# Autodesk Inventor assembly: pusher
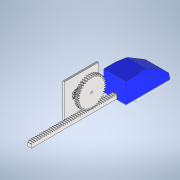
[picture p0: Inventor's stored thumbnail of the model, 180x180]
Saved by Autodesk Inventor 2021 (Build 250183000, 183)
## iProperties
Created: 2026-10
Part Number: pusher
Document SubType Name: Assembly
Designer: alolo
Author: alolo
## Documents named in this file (7)
- C:\Users\hp\Documents\Inventor\DOM1_CartesianRobot\pusher.iam
- C:\Users\hp\Documents\Inventor\DOM1_CartesianRobot\pusher_pinion.ipt
- C:\Users\hp\Documents\Inventor\DOM1_CartesianRobot\Servo MG996R.ipt
- C:\Users\hp\Documents\Inventor\DOM1_CartesianRobot\pusher_rack.ipt
- C:\Users\hp\Documents\Inventor\DOM1_CartesianRobot\pusher_base.ipt
- C:\Users\hp\Documents\Inventor\DOM1_CartesianRobot\pusher_support.ipt
- C:\Users\hp\Documents\Inventor\DOM1_CartesianRobot\pusher_punch.ipt
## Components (6 placed, 6 different names)
1. Servo MG996R:1 — Angle:1, Mate:8, Mate:9, Mate:10, Rotational:1
2. pusher_base:1 — Mate:1, Mate:2, Mate:11, Slider:2, Flush:2, Mate:14
3. pusher_support — Mate:8, Mate:9, Mate:10, Mate:11, Flush:2
4. pusher_pinion:1 — Rotational:1, Rotation/Translation:1, Flush:1
5. pusher_rack:1 — Slider:2, Rotation/Translation:1, Mate:12, Mate:13, Flush:1
6. pusher_punch:2 — Mate:12, Mate:13, Mate:14
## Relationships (15: Mate 9, Flush 2, Angle 1, RevoluteJoint 1, TranslationJoint 1, RelateRotateTranslate 1)
- Mate:1: pusher_base:1
- Mate:2: pusher_base:1
- Angle:1: Servo MG996R:1
- Mate:8: Servo MG996R:1 ↔ pusher_support
- Mate:9: Servo MG996R:1 ↔ pusher_support
- Mate:10: Servo MG996R:1 ↔ pusher_support
- Rotational:1 [RevoluteJoint]: Servo MG996R:1 ↔ pusher_pinion:1
- Mate:11: pusher_base:1 ↔ pusher_support
- Slider:2 [TranslationJoint]: pusher_base:1 ↔ pusher_rack:1
- Rotation/Translation:1 [RelateRotateTranslate]: pusher_pinion:1 ↔ pusher_rack:1
- Mate:12: pusher_rack:1 ↔ pusher_punch:2
- Mate:13: pusher_rack:1 ↔ pusher_punch:2
- Flush:1: pusher_pinion:1 ↔ pusher_rack:1
- Flush:2: pusher_base:1 ↔ pusher_support
- Mate:14: pusher_base:1 ↔ pusher_punch:2
